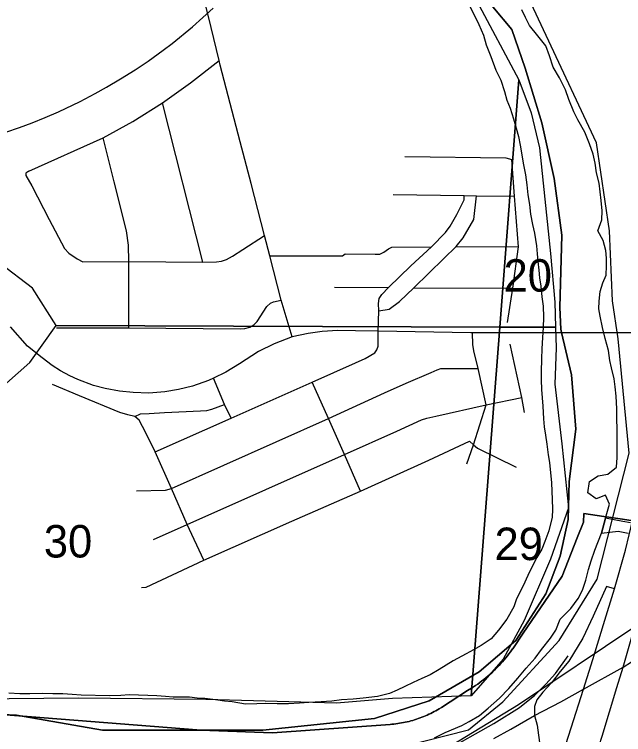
# Model space of a CAD drawing. Extents: x 0 to 34, y 0 to 22.
# Drawn here: x 6.478 to 7.262, y 15.184 to 16.112 of the extents above; entities that cross this region are included whole.
import ezdxf

# ---------------------------------------------------------------- set-up
doc = ezdxf.new("R2010")
doc.units = 0
for name, color, linetype in [('GM_X_City_Street', 7, 'Continuous'), ('GM_X_County_Road', 7, 'Continuous'), ('GM_X_Interchange_Ramps', 7, 'Continuous'), ('GM_X_Interstate_Route', 7, 'Continuous'), ('GM_X_Major_River', 7, 'Continuous'), ('GM_X_Minor_River', 7, 'Continuous'), ('GM_X_Rail_Line', 7, 'Continuous'), ('GM_X_Section', 7, 'Continuous'), ('GM_X_Section_Text', 7, 'Continuous')]:
    doc.layers.add(name, color=color, linetype=linetype)

msp = doc.modelspace()

# ---------------------------------------------------------------- linework, layer by layer
at = {"layer": 'GM_X_City_Street'}
for p, q in [((6.72051, 15.79311), (6.66873, 15.99838)), ((7.04702, 15.81333), (7.12722, 15.81299)), ((6.89005, 15.76065), (6.95987, 15.76029)), ((6.99229, 15.75988), (7.11969, 15.7597))]:
    msp.add_line(p, q, dxfattribs=at)
for points in [[(6.743, 16.04696), (6.74147, 16.05285), (6.72801, 16.10952), (6.71675, 16.15334), (6.70194, 16.21051), (6.69176, 16.2514), (6.72606, 16.29191), (6.76291, 16.33278)], [(6.49668, 15.91043), (6.59234, 15.9534), (6.63035, 15.97433), (6.66873, 15.99838), (6.70472, 16.0239), (6.74147, 16.05285)], [(6.83545, 15.69666), (6.82151, 15.74419), (6.80686, 15.80103), (6.8001, 15.82726), (6.78285, 15.89446), (6.76877, 15.94795), (6.743, 16.04696)], [(6.62519, 15.70853), (6.62505, 15.79369), (6.62494, 15.81502), (6.62225, 15.83362), (6.60646, 15.89642), (6.59234, 15.9534)], [(6.98091, 15.92898), (7.11062, 15.92731), (7.11864, 15.92551)], [(7.11284, 15.71536), (7.11969, 15.7597), (7.12722, 15.81299), (7.12202, 15.87813), (7.11864, 15.92551)], [(6.49668, 15.91043), (6.49246, 15.90768), (6.49273, 15.90456), (6.50044, 15.89143), (6.52259, 15.84803), (6.5422, 15.81081), (6.54809, 15.80466), (6.55888, 15.79716), (6.56613, 15.79345), (6.62505, 15.79369), (6.72051, 15.79311), (6.73838, 15.79354), (6.74445, 15.79454), (6.75119, 15.79665), (6.75886, 15.80095), (6.77218, 15.80917), (6.8001, 15.82726)], [(6.94634, 15.70411), (6.94713, 15.73025), (6.94696, 15.73992), (6.94773, 15.74624), (6.95093, 15.75148), (6.95987, 15.76029), (6.98866, 15.78819), (7.01505, 15.81271), (7.0333, 15.83145), (7.03891, 15.83937), (7.04781, 15.85448), (7.05713, 15.87344), (7.05731, 15.87889)], [(6.94713, 15.73025), (6.9606, 15.73247), (6.97407, 15.74229), (6.99229, 15.75988), (7.03075, 15.7978), (7.04702, 15.81333), (7.05592, 15.8243), (7.06973, 15.8482), (7.07306, 15.87871)], [(6.96555, 15.88011), (7.05731, 15.87889), (7.07306, 15.87871), (7.12202, 15.87813)], [(6.80686, 15.80103), (6.89558, 15.80102), (6.90027, 15.8011), (6.9039, 15.80382), (6.94255, 15.80324), (6.94839, 15.80353), (6.95348, 15.80591), (6.9595, 15.81017), (6.96406, 15.81245), (7.01505, 15.81271)], [(6.53224, 15.70848), (6.62519, 15.70853), (6.76871, 15.70694), (6.77469, 15.70749), (6.78123, 15.70948), (6.78627, 15.71232), (6.79056, 15.71648), (6.80317, 15.73607), (6.8077, 15.7401), (6.81161, 15.74194), (6.82151, 15.74419)], [(6.65908, 15.54875), (6.75722, 15.59218), (6.86136, 15.63827), (6.91718, 15.66323), (6.92976, 15.66913), (6.94207, 15.67607), (6.9446, 15.67995), (6.9465, 15.68478), (6.9465, 15.69112), (6.94634, 15.70411)], [(7.06057, 15.533), (7.06905, 15.55778), (7.08539, 15.60903), (7.07498, 15.65582), (7.06972, 15.67868), (7.06829, 15.68708), (7.06785, 15.70205)], [(7.1349, 15.59939), (7.13123, 15.61883), (7.11637, 15.68742)], [(6.63507, 15.49855), (6.67234, 15.4991), (6.68005, 15.50127), (6.8823, 15.59182), (6.95453, 15.62471), (6.98256, 15.63721), (7.01483, 15.65079), (7.02243, 15.65437), (7.02722, 15.65589), (7.07498, 15.65582)], [(6.75722, 15.59218), (6.7485, 15.60982), (6.73426, 15.64368)], [(6.92357, 15.49799), (6.90313, 15.54528), (6.8823, 15.59182), (6.86136, 15.63827)], [(6.72201, 15.40889), (6.70026, 15.45498), (6.68005, 15.50127), (6.65908, 15.54875), (6.65082, 15.56549), (6.643, 15.58146), (6.63843, 15.58929), (6.63289, 15.59428), (6.62409, 15.59646), (6.61355, 15.59928), (6.56161, 15.62069), (6.52695, 15.63535)], [(6.65683, 15.4355), (6.70026, 15.45498), (6.90313, 15.54528), (6.97043, 15.57541), (7.00201, 15.58998), (7.00896, 15.59193), (7.02074, 15.59463), (7.08539, 15.60903), (7.13123, 15.61883)], [(6.63289, 15.59428), (6.64039, 15.59743), (6.65125, 15.59798), (6.67135, 15.59928), (6.71753, 15.60156), (6.7259, 15.602), (6.73221, 15.60352), (6.7485, 15.60982)], [(6.64178, 15.37387), (6.64737, 15.37436), (6.72201, 15.40889), (6.83528, 15.45952), (6.92357, 15.49799), (7.01169, 15.53811), (7.06417, 15.56231), (7.06905, 15.55778), (7.0741, 15.55344), (7.12431, 15.52874)], [(6.88471, 15.08343), (6.88405, 15.09308), (6.88544, 15.09647), (6.88806, 15.0987), (6.89146, 15.09983), (6.9074, 15.10101), (6.91418, 15.10217), (6.92003, 15.10364), (6.92789, 15.10687), (6.9553, 15.12058), (6.99174, 15.14045), (7.03158, 15.16255), (7.09528, 15.1987), (7.12857, 15.21944), (7.13744, 15.2264), (7.14754, 15.23472), (7.16227, 15.24932), (7.17469, 15.26296), (7.19128, 15.28584)]]:
    msp.add_lwpolyline(points, dxfattribs=at)
at = {"layer": 'GM_X_County_Road'}
for points in [[(7.47353, 15.72586), (7.45788, 15.72185), (7.42366, 15.71108), (7.40766, 15.70712), (7.38802, 15.70411), (7.36267, 15.70205), (7.31007, 15.70205), (7.29135, 15.70199), (7.25843, 15.70189), (7.18291, 15.70178), (7.06785, 15.70205), (7.06584, 15.70209)], [(7.06584, 15.70209), (6.94634, 15.70411), (6.91703, 15.70474), (6.89454, 15.70498), (6.87426, 15.70364), (6.8562, 15.70094), (6.83545, 15.69666), (6.8124, 15.68779), (6.7922, 15.67797), (6.7678, 15.66197), (6.75022, 15.6512), (6.73426, 15.64368), (6.72804, 15.64074), (6.70729, 15.6333), (6.68907, 15.62886), (6.67156, 15.62601), (6.6512, 15.62442), (6.63077, 15.62498), (6.61318, 15.6268), (6.59481, 15.63036), (6.5796, 15.63425), (6.55964, 15.64201), (6.54926, 15.64653), (6.5373, 15.65294), (6.52637, 15.66007), (6.51354, 15.66973), (6.49469, 15.68494), (6.47282, 15.70981)], [(7.14765, 15.20875), (7.18182, 15.22667), (7.2107, 15.24278), (7.26173, 15.27124), (7.28342, 15.28506), (7.32329, 15.31313), (7.38989, 15.35718), (7.41451, 15.37521), (7.43025, 15.3858), (7.47919, 15.42692)], [(7.09518, 15.17935), (7.11743, 15.19118), (7.14765, 15.20875)]]:
    msp.add_lwpolyline(points, dxfattribs=at)
at = {"layer": 'GM_X_Interchange_Ramps'}
for points in [[(7.32243, 15.45244), (7.25787, 15.46218), (7.24337, 15.46436), (7.24025, 15.46483), (7.23702, 15.46532), (7.21145, 15.46918), (7.21089, 15.45818), (7.20288, 15.43788), (7.18334, 15.38841), (7.1332, 15.31481), (7.11965, 15.29491), (7.11947, 15.29467), (7.11687, 15.29106), (7.11488, 15.28842), (7.11285, 15.28581), (7.11077, 15.28324), (7.10864, 15.28071), (7.10647, 15.27822), (7.10426, 15.27576), (7.10201, 15.27334), (7.09971, 15.27096), (7.09738, 15.26862), (7.095, 15.26633), (7.09258, 15.26407), (7.09013, 15.26186), (7.08763, 15.25969), (7.0851, 15.25757), (7.08253, 15.25548), (7.07993, 15.25345), (7.07729, 15.25146), (7.07462, 15.24951), (7.07191, 15.24762), (7.06917, 15.24577), (7.0664, 15.24397), (7.06164, 15.24094), (7.02775, 15.21933), (7.02491, 15.21757), (7.02277, 15.2163), (7.02062, 15.21508), (7.01844, 15.21389), (7.01625, 15.21274), (7.01403, 15.21162), (7.0118, 15.21055), (7.00954, 15.20951), (7.00727, 15.20852), (7.00499, 15.20756), (7.00268, 15.20665), (7.00036, 15.20577), (6.99803, 15.20494), (6.99568, 15.20415), (6.99336, 15.20341), (6.99332, 15.20339), (6.99327, 15.20338), (6.99094, 15.20268), (6.98856, 15.20201), (6.98616, 15.20139), (6.98375, 15.2008), (6.98133, 15.20026), (6.9789, 15.19976), (6.97646, 15.1993), (6.97402, 15.19888), (6.97157, 15.19851), (6.96911, 15.19818), (6.96665, 15.19789), (6.96418, 15.19764), (6.96171, 15.19744), (6.81038, 15.18643), (6.72979, 15.18981), (6.71268, 15.19053), (6.37924, 15.21683)], [(6.37924, 15.21683), (6.71268, 15.19053), (6.72979, 15.18981), (6.81038, 15.18643), (6.96171, 15.19744), (6.96418, 15.19764), (6.96665, 15.19789), (6.96911, 15.19818), (6.97157, 15.19851), (6.97402, 15.19888), (6.97646, 15.1993), (6.9789, 15.19976), (6.98133, 15.20026), (6.98375, 15.2008), (6.98616, 15.20139), (6.98856, 15.20201), (6.99094, 15.20268), (6.99327, 15.20338), (6.99336, 15.20341), (6.99568, 15.20415), (6.99803, 15.20494), (7.00036, 15.20577), (7.00268, 15.20665), (7.00499, 15.20756), (7.00727, 15.20852), (7.00954, 15.20951), (7.0118, 15.21055), (7.01403, 15.21162), (7.01625, 15.21274), (7.01844, 15.21389), (7.02062, 15.21508), (7.02277, 15.2163), (7.02491, 15.21757), (7.02775, 15.21933), (7.06164, 15.24094), (7.0664, 15.24397), (7.06917, 15.24577), (7.07191, 15.24762), (7.07462, 15.24951), (7.07729, 15.25146), (7.07993, 15.25345), (7.08253, 15.25548), (7.0851, 15.25757), (7.08763, 15.25969), (7.09013, 15.26186), (7.09258, 15.26407), (7.095, 15.26633), (7.09738, 15.26862), (7.09971, 15.27096), (7.10201, 15.27334), (7.10426, 15.27576), (7.10647, 15.27822), (7.10864, 15.28071), (7.11077, 15.28324), (7.11285, 15.28581), (7.11488, 15.28842), (7.11687, 15.29106), (7.11947, 15.29467), (7.11965, 15.29491), (7.1332, 15.31481), (7.18334, 15.38841), (7.20288, 15.43788), (7.21089, 15.45818), (7.21145, 15.46918), (7.23702, 15.46532), (7.24025, 15.46483), (7.24337, 15.46436), (7.25787, 15.46218), (7.32243, 15.45244)], [(7.25071, 15.37198), (7.24025, 15.37522), (7.22344, 15.33688), (7.20996, 15.30849), (7.19174, 15.27914), (7.18097, 15.26552)], [(7.18097, 15.26552), (7.16949, 15.25098), (7.15837, 15.23915), (7.15056, 15.22921), (7.14772, 15.22069), (7.14765, 15.20875)], [(7.14765, 15.20875), (7.15098, 15.19647), (7.15482, 15.16769), (7.15198, 15.14189), (7.14678, 15.09741), (7.14133, 15.06681), (7.15377, 15.06297)]]:
    msp.add_lwpolyline(points, dxfattribs=at)
at = {"layer": 'GM_X_Interstate_Route'}
for points in [[(6.3782, 15.21419), (6.48068, 15.2093), (6.59154, 15.18985), (6.79771, 15.18987), (6.94171, 15.20505), (7.01187, 15.22799), (7.0763, 15.26526), (7.12355, 15.3054), (7.16222, 15.3656), (7.18084, 15.41433), (7.19087, 15.46163), (7.1923, 15.51036), (7.2009, 15.57773), (7.19518, 15.64797), (7.18268, 15.70231), (7.18166, 15.70671), (7.18015, 15.7347), (7.18302, 15.82787), (7.173, 15.90097), (7.15726, 15.97264), (7.13579, 16.04288), (7.11861, 16.09304), (7.09425, 16.12211)], [(7.09425, 16.12211), (7.11861, 16.09304), (7.13579, 16.04288), (7.15726, 15.97264), (7.173, 15.90097), (7.18302, 15.82787), (7.18015, 15.7347), (7.18166, 15.70671), (7.18268, 15.70231), (7.19518, 15.64797), (7.2009, 15.57773), (7.1923, 15.51036), (7.19087, 15.46163), (7.18084, 15.41433), (7.16222, 15.3656), (7.12355, 15.3054), (7.0763, 15.26526), (7.01187, 15.22799), (6.94171, 15.20505), (6.79771, 15.18987), (6.59154, 15.18985), (6.48068, 15.2093), (6.3782, 15.21419)], [(7.25071, 15.37198), (7.26473, 15.42187), (7.27444, 15.46151), (7.28217, 15.50379), (7.28858, 15.55182), (7.2922, 15.59558), (7.29305, 15.62692)], [(7.25391, 15.24515), (7.26173, 15.27124), (7.27498, 15.31637), (7.28507, 15.36134), (7.29465, 15.41276), (7.30218, 15.45587), (7.30284, 15.46179)], [(7.11101, 14.92951), (7.12049, 14.96137), (7.13235, 14.99506), (7.13711, 15.00858), (7.15377, 15.06297), (7.1717, 15.12066), (7.195, 15.19303), (7.2107, 15.24278), (7.22281, 15.28115), (7.23679, 15.32606), (7.25071, 15.37198)], [(7.15895, 14.93889), (7.18177, 15.01078), (7.19383, 15.0523), (7.21176, 15.10999), (7.23506, 15.18236), (7.25391, 15.24515)]]:
    msp.add_lwpolyline(points, dxfattribs=at)
at = {"layer": 'GM_X_Major_River'}
msp.add_line((7.2341, 15.44386), (7.23921, 15.46331), dxfattribs=at)
for points in [[(7.06234, 16.12697), (7.07037, 16.11083), (7.07584, 16.0993), (7.08202, 16.08547), (7.08557, 16.07322), (7.09134, 16.05788), (7.09783, 16.04024), (7.10441, 16.02755), (7.10906, 16.01299), (7.11225, 16.00189), (7.11622, 15.99153), (7.12089, 15.97774), (7.12407, 15.96587), (7.12727, 15.95477), (7.12932, 15.94369), (7.13136, 15.93146), (7.13304, 15.92039), (7.13617, 15.90548), (7.13781, 15.8925), (7.13908, 15.87991), (7.14111, 15.86731), (7.14276, 15.85471), (7.14516, 15.84172), (7.14759, 15.83025), (7.15031, 15.8142), (7.15125, 15.80391), (7.1522, 15.79399), (7.15311, 15.78255), (7.15406, 15.77301), (7.15574, 15.76193), (7.15738, 15.74857), (7.15904, 15.73636), (7.15952, 15.72226), (7.15888, 15.70895), (7.15787, 15.69602), (7.1572, 15.68118), (7.15657, 15.66863), (7.15624, 15.65188), (7.15642, 15.6416), (7.15694, 15.62902), (7.15749, 15.61835), (7.15841, 15.60729), (7.15923, 15.59128), (7.16017, 15.58098), (7.16186, 15.57029), (7.16352, 15.55845), (7.16553, 15.54471)], [(7.23513, 15.70899), (7.23238, 15.72351), (7.23067, 15.73306), (7.23087, 15.74296), (7.23224, 15.75512), (7.23588, 15.76647), (7.23987, 15.77629), (7.24048, 15.78846), (7.2403, 15.79837), (7.23973, 15.80828), (7.23619, 15.82091), (7.22922, 15.83323), (7.23443, 15.8476), (7.23466, 15.8594), (7.2334, 15.87237), (7.2321, 15.88381), (7.23081, 15.89488), (7.22765, 15.90827), (7.22599, 15.92048), (7.22319, 15.93234), (7.21851, 15.94538), (7.21236, 15.96073), (7.20357, 15.97651), (7.19846, 15.98689), (7.19194, 16.00262), (7.18763, 16.01527), (7.17997, 16.03065), (7.17188, 16.04413), (7.16686, 16.0587), (7.16218, 16.07173), (7.15181, 16.08487), (7.14107, 16.09803), (7.13634, 16.1084), (7.13159, 16.11801)], [(7.23921, 15.46331), (7.24433, 15.48112), (7.23926, 15.49302), (7.22702, 15.48831), (7.21655, 15.49575), (7.21835, 15.51056), (7.22987, 15.51757), (7.24206, 15.52), (7.25324, 15.52892), (7.25424, 15.54146), (7.2541, 15.55365), (7.25437, 15.56735), (7.2542, 15.57802), (7.25369, 15.59097), (7.25395, 15.60391), (7.25275, 15.62031), (7.25147, 15.63252), (7.25015, 15.64282), (7.24702, 15.65698), (7.24493, 15.66653), (7.2429, 15.67914), (7.23865, 15.69483), (7.23513, 15.70899)], [(7.16553, 15.54471), (7.16723, 15.53478), (7.16849, 15.52143), (7.16977, 15.50922), (7.16992, 15.49741), (7.17048, 15.4875), (7.17098, 15.47417), (7.1704, 15.46428), (7.16627, 15.44684), (7.16107, 15.43324), (7.15709, 15.42342), (7.1508, 15.4125), (7.14528, 15.40195), (7.13935, 15.3895), (7.13301, 15.37591), (7.12472, 15.35932), (7.1211, 15.34873), (7.11206, 15.33292), (7.10155, 15.31904), (7.09184, 15.3078), (7.07916, 15.29929), (7.06918, 15.2934), (7.05959, 15.28825), (7.04311, 15.27944), (7.02506, 15.26836), (7.01354, 15.26135), (7.00283, 15.25661), (6.99134, 15.25151), (6.98062, 15.24638), (6.97104, 15.24162), (6.96109, 15.23724), (6.94546, 15.23336), (6.92721, 15.23105), (6.91429, 15.23016), (6.89909, 15.22893), (6.88654, 15.22727), (6.87286, 15.22639), (6.85729, 15.22555), (6.84513, 15.22464), (6.83071, 15.22416), (6.81629, 15.22406), (6.80188, 15.22434), (6.79011, 15.22381), (6.77531, 15.22371), (6.75829, 15.22633), (6.74844, 15.22728), (6.73672, 15.22903), (6.72309, 15.23081), (6.71324, 15.23139), (6.7034, 15.23234), (6.69392, 15.23252), (6.68254, 15.23274), (6.67268, 15.23331), (6.66132, 15.2343), (6.64957, 15.23491), (6.62568, 15.23537), (6.61505, 15.23481), (6.60024, 15.23434), (6.56384, 15.23504), (6.55209, 15.23603), (6.54034, 15.23664), (6.52745, 15.23689), (6.51418, 15.23715), (6.49786, 15.2367), (6.48496, 15.23695), (6.47056, 15.23761)], [(7.01878, 15.18017), (7.03258, 15.18714), (7.05399, 15.19586), (7.06359, 15.20138), (7.07701, 15.20874), (7.0882, 15.21842), (7.10249, 15.23146), (7.11487, 15.24378), (7.12613, 15.25689), (7.13701, 15.27), (7.14864, 15.28272), (7.15683, 15.29398), (7.1685, 15.3086), (7.17514, 15.31875), (7.18074, 15.33311), (7.19467, 15.34693), (7.20402, 15.35969), (7.20954, 15.37024), (7.21397, 15.38348), (7.21727, 15.39712), (7.22052, 15.4081), (7.22535, 15.42209), (7.2341, 15.44386)]]:
    msp.add_lwpolyline(points, dxfattribs=at)
at = {"layer": 'GM_X_Minor_River'}
msp.add_line((7.23921, 15.46331), (7.2341, 15.44386), dxfattribs=at)
for points in [[(7.27156, 15.45699), (7.26135, 15.45909), (7.23921, 15.46331)], [(7.2341, 15.44386), (7.25542, 15.44664), (7.26826, 15.44373)]]:
    msp.add_lwpolyline(points, dxfattribs=at)
at = {"layer": 'GM_X_Rail_Line'}
for points in [[(6.46704, 15.96044), (6.48453, 15.96659), (6.50056, 15.97275), (6.5174, 15.97955), (6.53473, 15.98684), (6.56253, 16.00004), (6.58181, 16.01035), (6.59665, 16.01868), (6.61448, 16.02927), (6.63322, 16.04104), (6.65005, 16.05217), (6.66951, 16.0662), (6.68101, 16.07498), (6.70717, 16.09625), (6.73387, 16.12024)], [(5.01732, 14.00189), (5.07199, 14.06435), (5.12947, 14.11429), (5.176, 14.15127), (5.27919, 14.22824), (5.31365, 14.25269), (5.49073, 14.33558), (5.78364, 14.48073), (6.17515, 14.70175), (6.29306, 14.76767), (6.5502, 14.90974), (6.59183, 14.93964), (6.85985, 15.08152), (6.90635, 15.10076), (7.03045, 15.16419), (7.12702, 15.2232), (7.27714, 15.32361), (7.37171, 15.41695), (7.56811, 15.60595)]]:
    msp.add_lwpolyline(points, dxfattribs=at)
at = {"layer": 'GM_X_Section'}
for points in [[(6.09477, 16.78977), (6.9844, 16.78381), (6.9873, 16.61522), (6.99716, 16.39347), (7.04096, 16.20405), (7.0729, 16.13035), (7.12741, 16.02783), (7.1029, 15.70941), (6.53181, 15.71138), (6.50128, 15.75968), (6.45909, 15.79152), (6.39202, 15.85072), (6.31252, 15.89311), (6.25721, 15.91271), (6.20218, 15.92624), (6.20201, 15.92635), (6.08607, 15.92414)], [(7.09775, 16.22381), (7.80451, 16.16627), (7.71554, 15.1965), (6.67904, 14.83565), (6.71778, 15.14511), (6.8557, 15.14859), (6.94949, 15.1616), (7.06251, 15.19054), (7.10674, 15.22645), (7.17942, 15.30576), (7.22862, 15.38475), (7.26952, 15.54684), (7.25562, 15.69442), (7.2482, 15.74304), (7.24421, 15.83325), (7.22739, 15.94681)], [(7.17475, 15.70945), (7.1029, 15.70941), (7.12741, 16.02783), (7.14332, 15.98531), (7.15407, 15.94053), (7.16124, 15.87425), (7.1684, 15.80439), (7.17377, 15.74169)], [(6.53181, 15.71138), (7.1029, 15.70941), (7.06636, 15.2344), (6.96479, 15.23062), (6.89273, 15.22478), (6.72428, 15.22944), (6.56071, 15.23137), (6.42548, 15.23011), (6.30096, 15.27524), (6.2578, 15.31657), (6.3561, 15.53023), (6.3994, 15.57714), (6.49759, 15.66355)], [(7.1029, 15.70941), (7.17475, 15.70945), (7.17557, 15.68258), (7.17377, 15.636), (7.18273, 15.55897), (7.19169, 15.47657), (7.1684, 15.41029), (7.13437, 15.33148), (7.1075, 15.28132), (7.06636, 15.2344)]]:
    msp.add_lwpolyline(points, close=True, dxfattribs=at)

# ---------------------------------------------------------------- texts
at = {"layer": 'GM_X_Section_Text'}
for s, p in [('20', (7.10793, 15.75501)), ('30', (6.51585, 15.4125)), ('29', (7.09626, 15.40917))]:
    msp.add_text(s, height=0.041856, rotation=0.00001, dxfattribs=at).set_placement(p)

doc.saveas('drawing.dxf')
